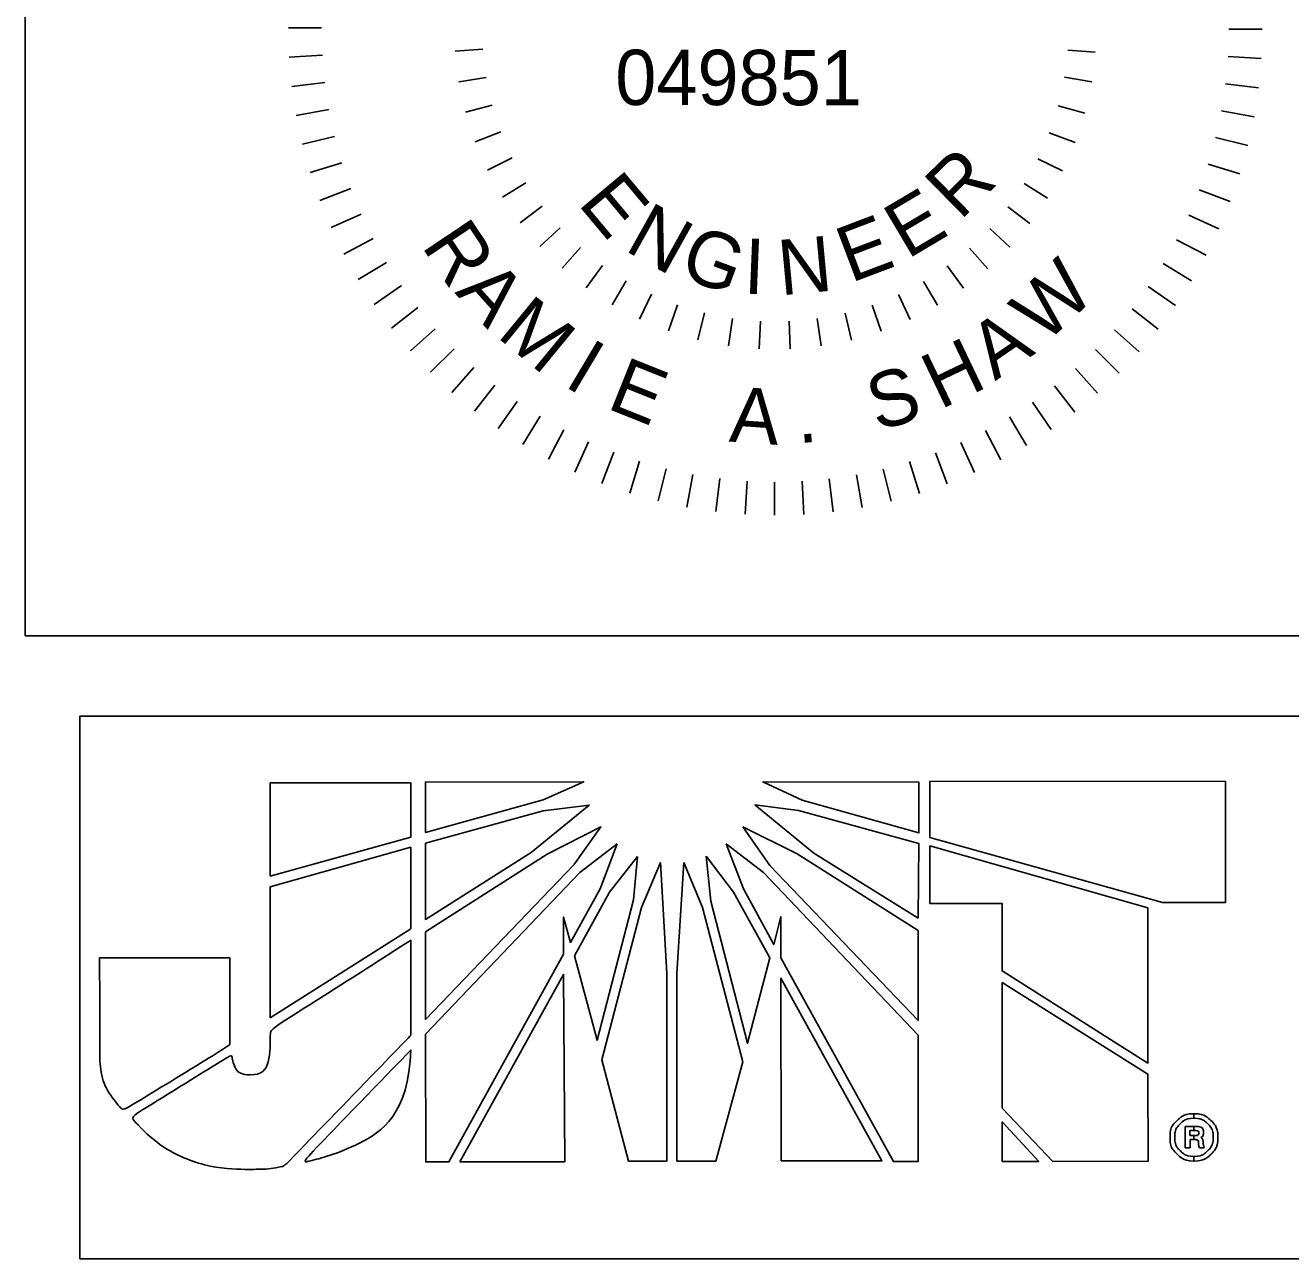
# Model space of a CAD drawing. Extents: x 2294370 to 2294957, y 719276 to 719941.
# Drawn here: x 2294735.99 to 2294757.04, y 719453.46 to 719473.99 of the extents above; entities that cross this region are included whole.
import ezdxf

# ---------------------------------------------------------------- set-up
doc = ezdxf.new("R2010")
doc.units = 0
for name, color, linetype in [('Default', 7, 'Continuous'), ('Old_Level_11', 7, 'Continuous'), ('Sheet Plan CELL', 7, 'Continuous')]:
    doc.layers.add(name, color=color, linetype=linetype)

msp = doc.modelspace()

# ---------------------------------------------------------------- linework, layer by layer
at = {"layer": 'Default'}
for p, q in [((2294740.367, 719473.945), (2294740.92, 719473.944)), ((2294756.567, 719473.922), (2294756.015, 719473.923)), ((2294740.382, 719473.456), (2294740.933, 719473.488)), ((2294743.142, 719473.554), (2294743.601, 719473.587)), ((2294753.792, 719473.539), (2294753.333, 719473.573)), ((2294756.552, 719473.433), (2294756.001, 719473.467)), ((2294740.425, 719472.969), (2294740.973, 719473.034)), ((2294743.204, 719473.042), (2294743.657, 719473.119)), ((2294753.278, 719473.121), (2294753.732, 719473.044)), ((2294756.507, 719472.946), (2294755.959, 719473.013)), ((2294743.314, 719472.538), (2294743.758, 719472.658)), ((2294753.617, 719472.523), (2294753.173, 719472.645)), ((2294740.498, 719472.485), (2294741.041, 719472.583)), ((2294756.433, 719472.462), (2294755.89, 719472.562)), ((2294743.473, 719472.047), (2294743.903, 719472.21)), ((2294753.456, 719472.033), (2294753.027, 719472.197)), ((2294740.6, 719472.007), (2294741.136, 719472.137)), ((2294756.33, 719471.984), (2294755.794, 719472.116)), ((2294743.679, 719471.575), (2294744.091, 719471.778)), ((2294753.249, 719471.561), (2294752.838, 719471.766)), ((2294740.73, 719471.534), (2294741.259, 719471.698)), ((2294756.198, 719471.512), (2294755.67, 719471.677)), ((2294743.928, 719471.124), (2294744.32, 719471.365)), ((2294752.999, 719471.111), (2294752.608, 719471.353)), ((2294740.889, 719471.072), (2294741.406, 719471.267)), ((2294756.037, 719471.051), (2294755.521, 719471.247)), ((2294744.221, 719470.698), (2294744.587, 719470.977)), ((2294752.705, 719470.686), (2294752.339, 719470.966)), ((2294741.077, 719470.62), (2294741.58, 719470.845)), ((2294755.849, 719470.599), (2294755.346, 719470.826)), ((2294744.553, 719470.304), (2294744.89, 719470.616)), ((2294752.371, 719470.293), (2294752.035, 719470.606)), ((2294741.29, 719470.179), (2294741.779, 719470.435)), ((2294744.921, 719469.943), (2294745.227, 719470.287)), ((2294755.635, 719470.159), (2294755.146, 719470.416)), ((2294752.002, 719469.933), (2294751.697, 719470.278)), ((2294741.53, 719469.753), (2294742.002, 719470.038)), ((2294745.323, 719469.619), (2294745.594, 719469.991)), ((2294751.599, 719469.61), (2294751.33, 719469.983)), ((2294755.393, 719469.733), (2294754.922, 719470.02)), ((2294741.795, 719469.341), (2294742.249, 719469.654)), ((2294745.754, 719469.336), (2294745.989, 719469.732)), ((2294751.168, 719469.328), (2294750.934, 719469.725)), ((2294746.211, 719469.096), (2294746.406, 719469.513)), ((2294750.71, 719469.089), (2294750.517, 719469.507)), ((2294755.127, 719469.323), (2294754.673, 719469.637)), ((2294742.084, 719468.948), (2294742.519, 719469.287)), ((2294746.689, 719468.9), (2294746.842, 719469.334)), ((2294750.232, 719468.895), (2294750.08, 719469.33)), ((2294754.837, 719468.929), (2294754.403, 719469.27)), ((2294747.29, 719469.199), (2294747.179, 719468.752)), ((2294747.689, 719468.652), (2294747.756, 719469.107)), ((2294748.202, 719468.601), (2294748.224, 719469.061)), ((2294748.718, 719468.6), (2294748.697, 719469.06)), ((2294749.231, 719468.65), (2294749.166, 719469.105)), ((2294749.738, 719468.748), (2294749.628, 719469.196)), ((2294742.397, 719468.571), (2294742.811, 719468.936)), ((2294754.523, 719468.553), (2294754.11, 719468.92)), ((2294742.732, 719468.214), (2294743.123, 719468.604)), ((2294754.187, 719468.198), (2294753.797, 719468.589)), ((2294743.087, 719467.878), (2294743.454, 719468.291)), ((2294753.83, 719467.863), (2294753.465, 719468.277)), ((2294743.463, 719467.564), (2294743.804, 719467.998)), ((2294753.453, 719467.55), (2294753.114, 719467.985)), ((2294743.857, 719467.274), (2294744.171, 719467.727)), ((2294753.059, 719467.261), (2294752.746, 719467.715)), ((2294744.267, 719467.008), (2294744.554, 719467.479)), ((2294752.648, 719466.996), (2294752.363, 719467.468)), ((2294744.693, 719466.766), (2294744.95, 719467.255)), ((2294752.222, 719466.756), (2294751.966, 719467.245)), ((2294745.133, 719466.552), (2294745.36, 719467.055)), ((2294751.781, 719466.543), (2294751.556, 719467.046)), ((2294745.584, 719466.363), (2294745.781, 719466.88)), ((2294746.046, 719466.203), (2294746.211, 719466.731)), ((2294750.867, 719466.196), (2294750.703, 719466.725)), ((2294751.329, 719466.355), (2294751.133, 719466.872)), ((2294746.518, 719466.071), (2294746.65, 719466.607)), ((2294746.996, 719465.968), (2294747.096, 719466.511)), ((2294749.916, 719465.964), (2294749.818, 719466.507)), ((2294750.394, 719466.066), (2294750.264, 719466.602)), ((2294747.48, 719465.894), (2294747.547, 719466.442)), ((2294747.967, 719465.849), (2294748.001, 719466.4)), ((2294748.456, 719465.834), (2294748.457, 719466.386)), ((2294748.945, 719465.848), (2294748.913, 719466.399)), ((2294749.432, 719465.891), (2294749.367, 719466.439))]:
    msp.add_line(p, q, dxfattribs=at)
at = {"layer": 'Old_Level_11'}
for p, q in [((2294742.403, 719461.382), (2294740.062, 719461.38)), ((2294740.062, 719461.38), (2294740.064, 719459.827)), ((2294742.404, 719460.478), (2294742.403, 719461.382)), ((2294745.28, 719461.396), (2294742.646, 719461.394)), ((2294742.646, 719461.394), (2294742.647, 719460.556)), ((2294744.608, 719461.098), (2294745.28, 719461.396)), ((2294750.856, 719461.39), (2294748.261, 719461.399)), ((2294748.261, 719461.399), (2294748.918, 719461.091)), ((2294750.857, 719460.548), (2294750.856, 719461.39)), ((2294755.958, 719461.406), (2294751.038, 719461.402)), ((2294751.038, 719461.402), (2294751.039, 719460.498)), ((2294755.96, 719459.391), (2294755.958, 719461.406)), ((2294742.647, 719460.556), (2294744.608, 719461.098)), ((2294748.918, 719461.091), (2294750.857, 719460.548)), ((2294744.608, 719460.917), (2294742.647, 719460.374)), ((2294744.404, 719460.221), (2294745.373, 719461.01)), ((2294745.373, 719461.01), (2294744.608, 719460.917)), ((2294748.13, 719461.013), (2294749.112, 719460.21)), ((2294748.853, 719460.921), (2294748.13, 719461.013)), ((2294750.857, 719460.37), (2294748.853, 719460.921)), ((2294745.566, 719460.647), (2294744.675, 719460.195)), ((2294745.115, 719460.014), (2294745.566, 719460.647)), ((2294747.926, 719460.65), (2294748.378, 719460.005)), ((2294748.83, 719460.199), (2294747.926, 719460.65)), ((2294740.064, 719459.827), (2294742.404, 719460.478)), ((2294751.039, 719460.498), (2294751.039, 719460.471)), ((2294751.039, 719460.471), (2294754.913, 719459.39)), ((2294742.404, 719460.308), (2294740.064, 719459.65)), ((2294742.405, 719458.953), (2294742.404, 719460.308)), ((2294742.647, 719460.374), (2294742.648, 719459.108)), ((2294742.648, 719459.108), (2294744.404, 719460.221)), ((2294744.675, 719460.195), (2294742.648, 719458.903)), ((2294745.837, 719460.366), (2294745.216, 719459.886)), ((2294745.552, 719459.616), (2294745.837, 719460.366)), ((2294747.652, 719460.367), (2294747.939, 719459.618)), ((2294748.274, 719459.889), (2294747.652, 719460.367)), ((2294750.843, 719458.922), (2294748.83, 719460.199)), ((2294749.112, 719460.21), (2294750.843, 719459.131)), ((2294750.843, 719459.131), (2294750.857, 719460.37)), ((2294751.039, 719460.332), (2294751.039, 719460.317)), ((2294754.666, 719459.3), (2294751.039, 719460.332)), ((2294751.039, 719460.317), (2294751.04, 719459.374)), ((2294742.65, 719457.443), (2294745.115, 719460.014)), ((2294746.173, 719460.157), (2294745.71, 719459.562)), ((2294746.108, 719459.435), (2294746.173, 719460.157)), ((2294746.559, 719460.054), (2294746.24, 719459.304)), ((2294746.662, 719458.208), (2294746.559, 719460.054)), ((2294746.946, 719460.054), (2294746.828, 719458.208)), ((2294747.255, 719459.305), (2294746.946, 719460.054)), ((2294747.32, 719460.159), (2294747.398, 719459.409)), ((2294747.773, 719459.564), (2294747.32, 719460.159)), ((2294748.378, 719460.005), (2294750.845, 719457.424)), ((2294745.216, 719459.886), (2294742.65, 719457.196)), ((2294750.845, 719457.181), (2294748.274, 719459.889)), ((2294740.064, 719459.65), (2294740.066, 719457.468)), ((2294745.062, 719458.724), (2294745.552, 719459.616)), ((2294745.71, 719459.562), (2294745.128, 719458.504)), ((2294748.38, 719458.468), (2294747.773, 719459.564)), ((2294747.939, 719459.618), (2294748.442, 719458.688)), ((2294745.504, 719457.098), (2294746.108, 719459.435)), ((2294747.398, 719459.409), (2294748.007, 719457.047)), ((2294751.04, 719459.374), (2294752.241, 719459.375)), ((2294752.241, 719459.375), (2294752.242, 719458.252)), ((2294754.913, 719459.39), (2294755.96, 719459.391)), ((2294744.947, 719458.53), (2294744.946, 719459.148)), ((2294744.946, 719459.148), (2294745.062, 719458.724)), ((2294746.24, 719459.304), (2294745.582, 719456.774)), ((2294747.93, 719456.737), (2294747.255, 719459.305)), ((2294748.442, 719458.688), (2294748.561, 719459.152)), ((2294748.561, 719459.152), (2294748.561, 719458.468)), ((2294754.669, 719456.717), (2294754.666, 719459.3)), ((2294740.066, 719457.468), (2294742.405, 719458.953)), ((2294750.845, 719457.424), (2294750.843, 719458.922)), ((2294742.648, 719458.903), (2294742.65, 719457.443)), ((2294743.038, 719455.072), (2294744.947, 719458.53)), ((2294745.128, 719458.504), (2294745.504, 719457.098)), ((2294748.007, 719457.047), (2294748.38, 719458.468)), ((2294748.561, 719458.468), (2294750.434, 719455.079)), ((2294744.947, 719458.194), (2294743.22, 719455.072)), ((2294744.965, 719455.074), (2294744.947, 719458.194)), ((2294746.665, 719455.087), (2294746.662, 719458.208)), ((2294746.828, 719458.208), (2294746.831, 719455.087)), ((2294750.241, 719455.091), (2294748.562, 719458.132)), ((2294748.562, 719458.132), (2294748.565, 719455.089)), ((2294752.242, 719458.252), (2294754.669, 719456.717)), ((2294752.242, 719458.058), (2294752.244, 719455.965)), ((2294754.669, 719456.535), (2294752.242, 719458.058)), ((2294742.65, 719457.196), (2294742.652, 719455.072)), ((2294750.847, 719455.08), (2294750.845, 719457.181)), ((2294745.582, 719456.774), (2294746.024, 719455.087)), ((2294747.479, 719455.088), (2294747.93, 719456.737)), ((2294754.67, 719455.083), (2294754.669, 719456.535)), ((2294752.244, 719455.965), (2294753.083, 719455.082)), ((2294755.432, 719455.874), (2294755.432, 719455.799)), ((2294755.432, 719455.799), (2294755.432, 719455.874)), ((2294752.851, 719455.082), (2294752.244, 719455.738)), ((2294752.244, 719455.738), (2294752.245, 719455.081)), ((2294755.286, 719455.305), (2294755.286, 719455.663)), ((2294755.286, 719455.663), (2294755.432, 719455.663)), ((2294755.432, 719455.594), (2294755.367, 719455.594)), ((2294755.367, 719455.594), (2294755.367, 719455.51)), ((2294755.432, 719455.663), (2294755.432, 719455.594)), ((2294755.432, 719455.594), (2294755.432, 719455.663)), ((2294755.432, 719455.663), (2294755.455, 719455.663)), ((2294755.442, 719455.594), (2294755.432, 719455.594)), ((2294755.367, 719455.51), (2294755.432, 719455.51)), ((2294755.433, 719455.445), (2294755.368, 719455.445)), ((2294755.368, 719455.445), (2294755.368, 719455.305)), ((2294755.432, 719455.51), (2294755.433, 719455.445)), ((2294755.433, 719455.445), (2294755.432, 719455.51)), ((2294755.432, 719455.51), (2294755.436, 719455.51)), ((2294755.436, 719455.445), (2294755.433, 719455.445)), ((2294755.368, 719455.305), (2294755.286, 719455.305)), ((2294755.433, 719455.165), (2294755.433, 719455.087)), ((2294755.433, 719455.087), (2294755.433, 719455.165)), ((2294755.433, 719455.165), (2294755.436, 719455.165)), ((2294742.652, 719455.072), (2294743.038, 719455.072)), ((2294743.22, 719455.072), (2294744.965, 719455.074)), ((2294746.024, 719455.087), (2294746.665, 719455.087)), ((2294746.831, 719455.087), (2294747.479, 719455.088)), ((2294748.565, 719455.089), (2294750.241, 719455.091)), ((2294750.434, 719455.079), (2294750.847, 719455.08)), ((2294752.245, 719455.081), (2294752.851, 719455.082)), ((2294753.083, 719455.082), (2294754.67, 719455.083)), ((2294755.436, 719455.087), (2294755.433, 719455.087))]:
    msp.add_line(p, q, dxfattribs=at)
msp.add_lwpolyline([(2294736.897, 719453.463), (2294786.907, 719453.463), (2294786.907, 719462.487), (2294736.897, 719462.487)], close=True, dxfattribs=at)
for points in [[(2294740.064, 719459.827), (2294742.404, 719460.478), (2294742.403, 719461.382), (2294740.062, 719461.38), (2294740.064, 719459.827)], [(2294744.608, 719461.098), (2294745.28, 719461.396), (2294742.646, 719461.394), (2294742.647, 719460.556), (2294744.608, 719461.098)], [(2294748.918, 719461.091), (2294750.857, 719460.548), (2294750.856, 719461.39), (2294748.261, 719461.399), (2294748.918, 719461.091)], [(2294755.958, 719461.406), (2294751.038, 719461.402), (2294751.039, 719460.498), (2294751.039, 719460.471), (2294754.913, 719459.39), (2294755.96, 719459.391), (2294755.958, 719461.406)], [(2294742.647, 719460.374), (2294742.648, 719459.108), (2294744.404, 719460.221), (2294745.373, 719461.01), (2294744.608, 719460.917), (2294742.647, 719460.374)], [(2294748.13, 719461.013), (2294749.112, 719460.21), (2294750.843, 719459.131), (2294750.857, 719460.37), (2294748.853, 719460.921), (2294748.13, 719461.013)], [(2294742.648, 719458.903), (2294742.65, 719457.443), (2294745.115, 719460.014), (2294745.566, 719460.647), (2294744.675, 719460.195), (2294742.648, 719458.903)], [(2294747.926, 719460.65), (2294748.378, 719460.005), (2294750.845, 719457.424), (2294750.843, 719458.922), (2294748.83, 719460.199), (2294747.926, 719460.65)], [(2294740.066, 719457.468), (2294742.405, 719458.953), (2294742.404, 719460.308), (2294740.064, 719459.65), (2294740.066, 719457.468)], [(2294745.837, 719460.366), (2294745.216, 719459.886), (2294742.65, 719457.196), (2294742.652, 719455.072), (2294743.038, 719455.072), (2294744.947, 719458.53), (2294744.946, 719459.148), (2294745.062, 719458.724), (2294745.552, 719459.616), (2294745.837, 719460.366)], [(2294747.652, 719460.367), (2294747.939, 719459.618), (2294748.442, 719458.688), (2294748.561, 719459.152), (2294748.561, 719458.468), (2294750.434, 719455.079), (2294750.847, 719455.08), (2294750.845, 719457.181), (2294748.274, 719459.889), (2294747.652, 719460.367)], [(2294751.039, 719460.332), (2294751.039, 719460.317), (2294751.04, 719459.374), (2294752.241, 719459.375), (2294752.242, 719458.252), (2294754.669, 719456.717), (2294754.666, 719459.3), (2294751.039, 719460.332)], [(2294746.173, 719460.157), (2294745.71, 719459.562), (2294745.128, 719458.504), (2294745.504, 719457.098), (2294746.108, 719459.435), (2294746.173, 719460.157)], [(2294746.24, 719459.304), (2294745.582, 719456.774), (2294746.024, 719455.087), (2294746.665, 719455.087), (2294746.662, 719458.208), (2294746.559, 719460.054), (2294746.24, 719459.304)], [(2294746.946, 719460.054), (2294746.828, 719458.208), (2294746.831, 719455.087), (2294747.479, 719455.088), (2294747.93, 719456.737), (2294747.255, 719459.305), (2294746.946, 719460.054)], [(2294747.32, 719460.159), (2294747.398, 719459.409), (2294748.007, 719457.047), (2294748.38, 719458.468), (2294747.773, 719459.564), (2294747.32, 719460.159)], [(2294743.22, 719455.072), (2294744.965, 719455.074), (2294744.947, 719458.194), (2294743.22, 719455.072)], [(2294748.565, 719455.089), (2294750.241, 719455.091), (2294748.562, 719458.132), (2294748.565, 719455.089)], [(2294752.242, 719458.058), (2294752.244, 719455.965), (2294753.083, 719455.082), (2294754.67, 719455.083), (2294754.669, 719456.535), (2294752.242, 719458.058), (2294752.242, 719458.058)], [(2294752.245, 719455.081), (2294752.245, 719455.081), (2294752.851, 719455.082), (2294752.244, 719455.738), (2294752.245, 719455.081)], [(2294755.589, 719455.39), (2294755.589, 719455.37), (2294755.592, 719455.357), (2294755.592, 719455.344), (2294755.602, 719455.305), (2294755.527, 719455.305)]]:
    msp.add_lwpolyline(points, dxfattribs=at)
for points, degree in [([(2294739.731, 719456.521), (2294739.592, 719456.521), (2294739.472, 719456.598), (2294739.422, 719456.857), (2294739.422, 719456.857), (2294737.743, 719455.816), (2294737.743, 719455.816), (2294738.261, 719455.272), (2294739.088, 719454.949), (2294739.787, 719454.949), (2294739.968, 719454.95), (2294740.107, 719454.965), (2294740.3, 719455.004), (2294740.3, 719455.004), (2294742.407, 719457.184), (2294742.407, 719457.184), (2294742.407, 719457.184), (2294742.405, 719458.76), (2294742.405, 719458.76), (2294742.405, 719458.76), (2294740.066, 719457.271), (2294740.066, 719457.271), (2294740.067, 719456.68), (2294739.924, 719456.521), (2294739.731, 719456.521)], 3), ([(2294739.731, 719456.521), (2294739.592, 719456.521), (2294739.472, 719456.598), (2294739.422, 719456.857), (2294739.422, 719456.857), (2294737.743, 719455.816), (2294737.743, 719455.816), (2294738.261, 719455.272), (2294739.088, 719454.949), (2294739.787, 719454.949), (2294739.968, 719454.95), (2294740.107, 719454.965), (2294740.3, 719455.004), (2294740.3, 719455.004), (2294742.407, 719457.184), (2294742.407, 719457.184), (2294742.407, 719457.184), (2294742.405, 719458.76), (2294742.405, 719458.76), (2294742.405, 719458.76), (2294740.066, 719457.271), (2294740.066, 719457.271), (2294740.067, 719456.68), (2294739.924, 719456.521), (2294739.731, 719456.521)], 3), ([(2294739.393, 719458.471), (2294739.393, 719458.471), (2294737.227, 719458.469), (2294737.227, 719458.469), (2294737.227, 719458.469), (2294737.228, 719457.113), (2294737.228, 719457.113), (2294737.228, 719457.113), (2294737.228, 719456.971), (2294737.228, 719456.971), (2294737.229, 719456.546), (2294737.368, 719456.21), (2294737.615, 719455.928), (2294737.615, 719455.928), (2294739.395, 719457.011), (2294739.395, 719457.038), (2294739.395, 719457.038), (2294739.393, 719458.471), (2294739.393, 719458.471)], 3), ([(2294742.407, 719456.937), (2294742.407, 719456.937), (2294740.586, 719455.054), (2294740.586, 719455.054), (2294741.478, 719455.275), (2294742.366, 719455.867), (2294742.407, 719456.937)], 3), ([(2294755.433, 719455.087), (2294755.326, 719455.087), (2294755.231, 719455.126), (2294755.153, 719455.204), (2294755.075, 719455.279), (2294755.036, 719455.373), (2294755.036, 719455.483), (2294755.036, 719455.594), (2294755.075, 719455.688), (2294755.153, 719455.76), (2294755.231, 719455.835), (2294755.322, 719455.874), (2294755.432, 719455.874)], 3), ([(2294755.432, 719455.799), (2294755.344, 719455.799), (2294755.27, 719455.77), (2294755.208, 719455.711), (2294755.146, 719455.649), (2294755.114, 719455.571), (2294755.114, 719455.484), (2294755.114, 719455.396), (2294755.146, 719455.318), (2294755.208, 719455.256), (2294755.27, 719455.194), (2294755.345, 719455.165), (2294755.433, 719455.165)], 3), ([(2294755.432, 719455.874), (2294755.543, 719455.874), (2294755.637, 719455.835), (2294755.715, 719455.761), (2294755.793, 719455.689), (2294755.832, 719455.595), (2294755.833, 719455.484)], 3), ([(2294755.436, 719455.165), (2294755.524, 719455.165), (2294755.599, 719455.195), (2294755.66, 719455.256), (2294755.722, 719455.318), (2294755.755, 719455.396), (2294755.755, 719455.484), (2294755.754, 719455.572), (2294755.722, 719455.65), (2294755.66, 719455.712), (2294755.598, 719455.77), (2294755.523, 719455.799), (2294755.432, 719455.799)], 3), ([(2294755.436, 719455.51), (2294755.488, 719455.51), (2294755.514, 719455.526), (2294755.514, 719455.555), (2294755.514, 719455.581), (2294755.491, 719455.594), (2294755.442, 719455.594)], 3), ([(2294755.455, 719455.663), (2294755.546, 719455.663), (2294755.592, 719455.627), (2294755.592, 719455.556), (2294755.592, 719455.523), (2294755.579, 719455.497), (2294755.55, 719455.477)], 3), ([(2294755.833, 719455.484), (2294755.833, 719455.374), (2294755.794, 719455.279), (2294755.719, 719455.201), (2294755.641, 719455.126), (2294755.547, 719455.087), (2294755.436, 719455.087)], 3), ([(2294755.498, 719455.432), (2294755.488, 719455.438), (2294755.468, 719455.445), (2294755.436, 719455.445)], 2), ([(2294755.527, 719455.305), (2294755.517, 719455.325), (2294755.511, 719455.344), (2294755.511, 719455.37), (2294755.511, 719455.403), (2294755.507, 719455.422), (2294755.498, 719455.432)], 3), ([(2294755.55, 719455.477), (2294755.572, 719455.464), (2294755.585, 719455.435), (2294755.589, 719455.39)], 2)]:
    msp.add_open_spline(points, degree=degree, dxfattribs=at)
at = {"layer": 'Sheet Plan CELL'}
msp.add_lwpolyline([(2294762.275, 719463.828), (2294735.99, 719463.828), (2294735.99, 719486.328), (2294762.275, 719486.328)], dxfattribs=at)

# ---------------------------------------------------------------- texts
at = {"layer": 'Default'}
for s, height, rotation, p in [('049851', 0.9194, 359.9186, (2294745.805, 719472.66)), ('R', 0.94, 44.4835, (2294751.543, 719470.725)), ('E', 0.94, 309.9887, (2294745.168, 719471.018)), ('E', 0.934, 30.7124, (2294750.666, 719470.085)), ('N', 0.933, 330.8438, (2294745.939, 719470.25)), ('R', 0.938, 303.8537, (2294742.57, 719470.318)), ('E', 0.928, 20.7266, (2294749.722, 719469.694)), ('G', 0.927, 339.61, (2294746.838, 719469.818)), ('I', 0.92, 357.7048, (2294747.933, 719469.522)), ('N', 0.92, 5.3345, (2294748.557, 719469.49)), ('W', 0.94, 43.2431, (2294752.954, 719468.666)), ('A', 0.94, 311.9255, (2294743.126, 719469.537)), ('M', 0.939, 320.5682, (2294743.814, 719468.812)), ('A', 0.937, 34.3604, (2294752.123, 719468.061)), ('I', 0.934, 329.2408, (2294744.932, 719467.995)), ('H', 0.931, 25.5378, (2294751.211, 719467.586)), ('E', 0.928, 338.2133, (2294745.643, 719467.62)), ('S', 0.925, 16.5353, (2294750.163, 719467.228)), ('A', 0.92, 356.0086, (2294747.69, 719467.06)), ('.', 0.92, 3.7509, (2294748.847, 719467.033))]:
    msp.add_text(s, height=height, rotation=rotation, dxfattribs=at).set_placement(p)

doc.saveas('drawing.dxf')
